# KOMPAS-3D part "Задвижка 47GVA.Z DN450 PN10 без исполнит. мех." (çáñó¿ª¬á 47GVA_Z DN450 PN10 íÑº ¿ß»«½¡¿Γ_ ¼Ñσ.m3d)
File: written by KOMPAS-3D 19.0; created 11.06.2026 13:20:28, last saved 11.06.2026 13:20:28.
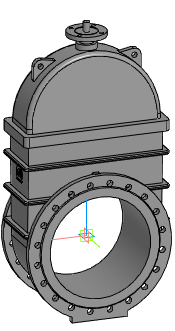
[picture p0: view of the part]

Document properties: Автор: Евгений; Полное имя файла: Z:\3.Личные\kachalov\001_3d для проектировщиков\2.2 Тип 47GVA, 47GVA.Z\_stp\_stp_Задвижка 47GVA.Z DN350-DN1200 без исп.мех\Задвижка 47GVA_Z DN450 PN10 без исполнит_ мех.m3d

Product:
- Part/product: Задвижка 47GVA.Z DN450 PN10 без исполнит. мех.

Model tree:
1. Операция без истории:1  (labels: Задвижка 47GVA.Z DN450 PN10 без исполнит. мех.)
